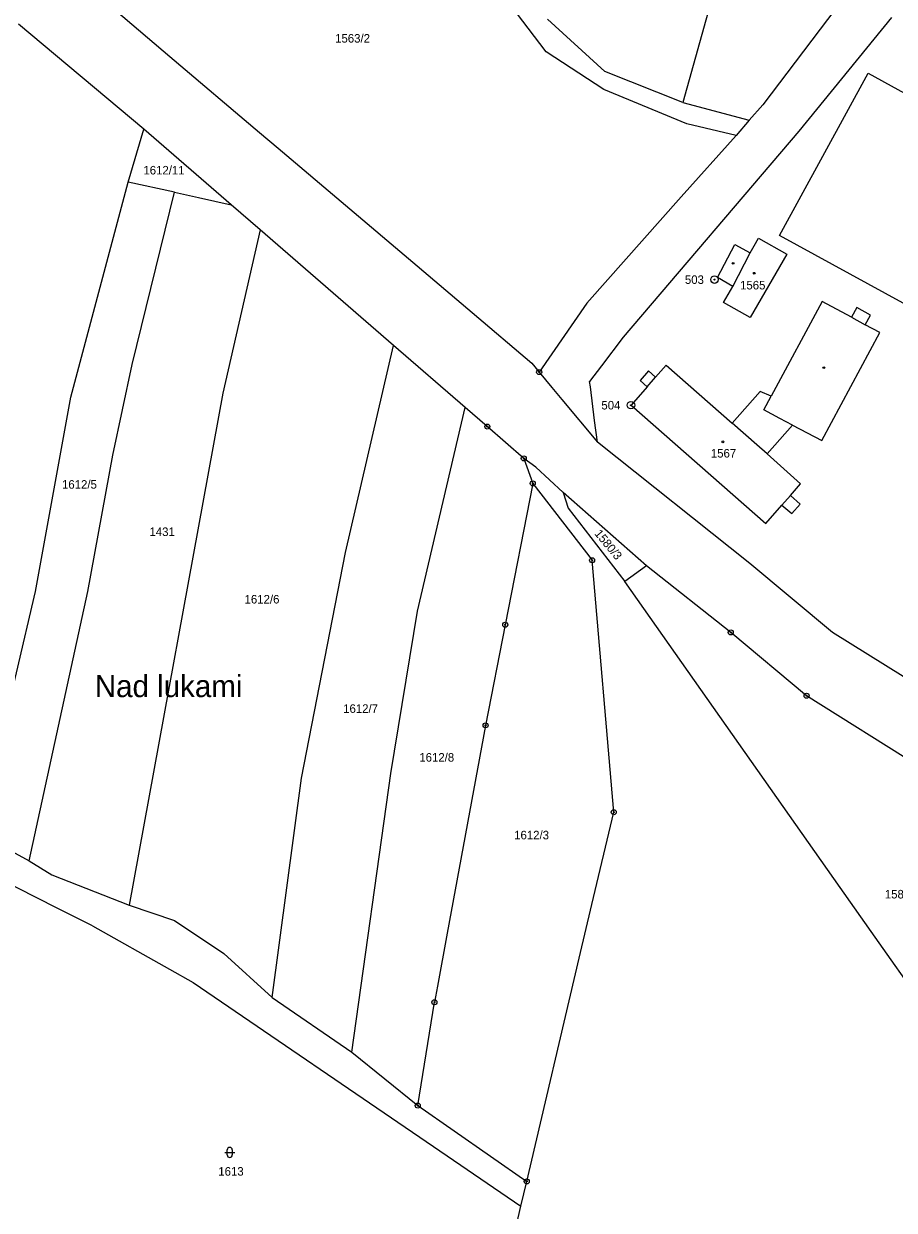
# Model space of a CAD drawing. Extents: x -763296 to -761805, y -1153670 to -1152034.
# Drawn here: x -762549.1 to -762375.6, y -1152539 to -1152302.6 of the extents above; entities that cross this region are included whole.
import ezdxf

# ---------------------------------------------------------------- set-up
doc = ezdxf.new("R2010")
doc.units = 0
for name, color, linetype in [('Vrstva 1', 7, 'Continuous'), ('Vrstva 15', 7, 'Continuous'), ('Vrstva 17', 7, 'Continuous'), ('Vrstva 18', 7, 'Continuous'), ('Vrstva 19', 7, 'Continuous'), ('Vrstva 24', 7, 'Continuous'), ('Vrstva 25', 7, 'Continuous'), ('Vrstva 4', 7, 'Continuous'), ('Vrstva 6', 7, 'Continuous')]:
    doc.layers.add(name, color=color, linetype=linetype)

msp = doc.modelspace()

# ---------------------------------------------------------------- linework, layer by layer
at = {"layer": 'Vrstva 1'}
for p, q in [((-762541.7, -1152290.61), (-762519.96, -1152309.07)), ((-762384.25, -1152295.59), (-762401.81, -1152318.76)), ((-762525.16, -1152323.58), (-762550.16, -1152302.68)), ((-762376.16, -1152301.32), (-762394.59, -1152324.01)), ((-762519.96, -1152309.07), (-762502.08, -1152324.24)), ((-762398.44, -1152344.76), (-762380.75, -1152312.44)), ((-762380.75, -1152312.44), (-762350.33, -1152329.15)), ((-762401.81, -1152318.76), (-762404.52, -1152321.81)), ((-762507.77, -1152338.63), (-762525.16, -1152323.58)), ((-762404.52, -1152321.81), (-762407.09, -1152324.84)), ((-762502.08, -1152324.24), (-762498.38, -1152327.38)), ((-762394.59, -1152324.01), (-762429.64, -1152365.01)), ((-762407.09, -1152324.84), (-762418.03, -1152337.04)), ((-762498.38, -1152327.38), (-762471.57, -1152350.11)), ((-762418.03, -1152337.04), (-762436.86, -1152358.25)), ((-762501.98, -1152343.64), (-762507.77, -1152338.63)), ((-762475.37, -1152366.68), (-762501.98, -1152343.64)), ((-762360.92, -1152365.36), (-762398.44, -1152344.76)), ((-762410.8, -1152353.16), (-762407.36, -1152346.54)), ((-762407.36, -1152346.54), (-762404.3, -1152348.24)), ((-762404.3, -1152348.24), (-762403.53, -1152346.85)), ((-762403.53, -1152346.85), (-762402.67, -1152345.3)), ((-762402.67, -1152345.3), (-762397.02, -1152348.51)), ((-762397.02, -1152348.51), (-762404.32, -1152361.1)), ((-762471.57, -1152350.11), (-762459.73, -1152360.14)), ((-762407.77, -1152354.91), (-762410.8, -1152353.16)), ((-762409.64, -1152358.14), (-762407.77, -1152354.91)), ((-762436.86, -1152358.25), (-762446.36, -1152371.99)), ((-762404.32, -1152361.1), (-762409.64, -1152358.14)), ((-762389.92, -1152357.94), (-762400.1, -1152376.82)), ((-762384.11, -1152361.07), (-762389.92, -1152357.94)), ((-762383.07, -1152359.13), (-762384.11, -1152361.07)), ((-762380.31, -1152360.62), (-762383.07, -1152359.13)), ((-762459.73, -1152360.14), (-762447.82, -1152370.24)), ((-762381.35, -1152362.56), (-762380.31, -1152360.62)), ((-762390.04, -1152385.62), (-762378.45, -1152364.12)), ((-762378.45, -1152364.12), (-762381.35, -1152362.56)), ((-762429.64, -1152365.01), (-762433.93, -1152370.74)), ((-762461.12, -1152379.02), (-762475.37, -1152366.68)), ((-762447.82, -1152370.24), (-762446.36, -1152371.99)), ((-762433.93, -1152370.74), (-762436.3, -1152373.89)), ((-762421.04, -1152370.62), (-762423.15, -1152373.01)), ((-762421.04, -1152370.62), (-762407.87, -1152382.18)), ((-762446.36, -1152371.99), (-762443.81, -1152375.06)), ((-762424.58, -1152371.75), (-762426.25, -1152373.65)), ((-762423.15, -1152373.01), (-762424.58, -1152371.75)), ((-762443.81, -1152375.06), (-762441.82, -1152377.45)), ((-762436.16, -1152374.96), (-762436.3, -1152373.89)), ((-762435.3, -1152381.66), (-762436.16, -1152374.96)), ((-762424.82, -1152374.91), (-762428.05, -1152378.58)), ((-762426.25, -1152373.65), (-762424.82, -1152374.91)), ((-762402.31, -1152375.88), (-762407.87, -1152382.18)), ((-762400.1, -1152376.82), (-762402.31, -1152375.88)), ((-762441.82, -1152377.45), (-762434.75, -1152385.96)), ((-762456.69, -1152382.85), (-762461.12, -1152379.02)), ((-762428.05, -1152378.58), (-762401.2, -1152402.17)), ((-762449.42, -1152389.19), (-762456.69, -1152382.85)), ((-762434.75, -1152385.96), (-762435.3, -1152381.66)), ((-762400.94, -1152388.31), (-762395.85, -1152382.56)), ((-762395.85, -1152382.56), (-762390.04, -1152385.62)), ((-762404.36, -1152410.13), (-762434.75, -1152385.96)), ((-762447, -1152390.96), (-762449.42, -1152389.19)), ((-762449.42, -1152389.19), (-762447.63, -1152394.18)), ((-762394.24, -1152394.24), (-762400.94, -1152388.31)), ((-762441.55, -1152395.98), (-762447, -1152390.96)), ((-762447.63, -1152394.18), (-762453.12, -1152422.34)), ((-762447.63, -1152394.18), (-762435.8, -1152409.5)), ((-762396.29, -1152396.58), (-762394.24, -1152394.24)), ((-762441.55, -1152395.98), (-762440.61, -1152399.1)), ((-762424.94, -1152410.59), (-762441.55, -1152395.98)), ((-762394.34, -1152398.3), (-762396.29, -1152396.58)), ((-762440.61, -1152399.1), (-762429.27, -1152413.7)), ((-762401.2, -1152402.17), (-762397.97, -1152398.49)), ((-762397.97, -1152398.49), (-762396.01, -1152400.2)), ((-762396.01, -1152400.2), (-762394.34, -1152398.3)), ((-762431.5, -1152459.7), (-762435.8, -1152409.5)), ((-762424.94, -1152410.59), (-762429.27, -1152413.7)), ((-762408.18, -1152423.87), (-762424.94, -1152410.59)), ((-762387.9, -1152423.92), (-762404.36, -1152410.13)), ((-762386.35, -1152474.7), (-762429.27, -1152413.7)), ((-762453.12, -1152422.34), (-762457.04, -1152442.39)), ((-762393.06, -1152436.49), (-762408.18, -1152423.87)), ((-762370.2, -1152434.94), (-762387.9, -1152423.92)), ((-762370.42, -1152450.7), (-762393.06, -1152436.49)), ((-762457.04, -1152442.39), (-762464.69, -1152483.78)), ((-762435.83, -1152478.1), (-762431.5, -1152459.7)), ((-762542.4, -1152478.84), (-762557.33, -1152471.3)), ((-762379.39, -1152484.58), (-762386.35, -1152474.7)), ((-762535.41, -1152482.36), (-762542.4, -1152478.84)), ((-762438.36, -1152488.8), (-762435.83, -1152478.1)), ((-762535.41, -1152482.36), (-762520.04, -1152490.99)), ((-762464.69, -1152483.78), (-762466.64, -1152494.34)), ((-762364.92, -1152505.15), (-762379.39, -1152484.58)), ((-762448.83, -1152533.27), (-762438.36, -1152488.8)), ((-762520.04, -1152490.99), (-762515.34, -1152493.63)), ((-762515.34, -1152493.63), (-762467.4, -1152526.31)), ((-762466.64, -1152494.34), (-762467.24, -1152497.57)), ((-762470.56, -1152518.17), (-762467.24, -1152497.57)), ((-762470.56, -1152518.17), (-762448.83, -1152533.27)), ((-762467.4, -1152526.31), (-762449.99, -1152538.18)), ((-762449.99, -1152538.18), (-762448.83, -1152533.27)), ((-762451.46, -1152544.43), (-762449.99, -1152538.18))]:
    msp.add_line(p, q, dxfattribs=at)
at = {"layer": 'Vrstva 24'}
for centre, radius in [((-762411.41, -1152353.57), 0.75), ((-762411.41, -1152353.57), 0.1), ((-762446.36, -1152371.99), 0.5), ((-762446.36, -1152371.99), 0.1), ((-762428.06, -1152378.59), 0.75), ((-762428.06, -1152378.59), 0.1), ((-762456.69, -1152382.85), 0.5), ((-762456.69, -1152382.85), 0.1), ((-762449.42, -1152389.19), 0.5), ((-762449.42, -1152389.19), 0.1), ((-762447.63, -1152394.18), 0.5), ((-762447.63, -1152394.18), 0.1), ((-762435.8, -1152409.5), 0.5), ((-762435.8, -1152409.5), 0.1), ((-762453.12, -1152422.34), 0.5), ((-762453.12, -1152422.34), 0.1), ((-762408.18, -1152423.87), 0.5), ((-762408.18, -1152423.87), 0.1), ((-762393.06, -1152436.49), 0.5), ((-762393.06, -1152436.49), 0.1), ((-762457.04, -1152442.39), 0.5), ((-762457.04, -1152442.39), 0.1), ((-762431.5, -1152459.7), 0.5), ((-762431.5, -1152459.7), 0.1), ((-762467.24, -1152497.57), 0.5), ((-762467.24, -1152497.57), 0.1), ((-762470.56, -1152518.17), 0.5), ((-762470.56, -1152518.17), 0.1), ((-762448.83, -1152533.27), 0.5), ((-762448.83, -1152533.27), 0.1)]:
    msp.add_circle(centre, radius, dxfattribs=at)
at = {"layer": 'Vrstva 25'}
for p, q in [((-762508.53, -1152528.01), (-762508.53, -1152527.01)), ((-762507.53, -1152527.01), (-762507.53, -1152528.01)), ((-762509.03, -1152527.51), (-762507.03, -1152527.51))]:
    msp.add_line(p, q, dxfattribs=at)
for centre in [(-762407.7, -1152350.32), (-762403.49, -1152352.3), (-762389.62, -1152371.11), (-762409.73, -1152385.89)]:
    msp.add_circle(centre, 0.175, dxfattribs=at)
for centre, start, end in [((-762508.03, -1152527.01), 0, 180), ((-762508.03, -1152528.01), 180, 0)]:
    msp.add_arc(centre, 0.5, start, end, dxfattribs=at)
at = {"layer": 'Vrstva 4'}
for p, q in [((-762407.77, -1152354.91), (-762404.3, -1152348.24)), ((-762384.11, -1152361.07), (-762381.35, -1152362.56)), ((-762424.82, -1152374.91), (-762423.15, -1152373.01)), ((-762401.55, -1152379.51), (-762400.1, -1152376.82)), ((-762398.36, -1152381.24), (-762401.55, -1152379.51)), ((-762403, -1152386.49), (-762407.87, -1152382.18)), ((-762395.85, -1152382.56), (-762398.36, -1152381.24)), ((-762400.94, -1152388.31), (-762403, -1152386.49)), ((-762397.97, -1152398.49), (-762396.29, -1152396.58))]:
    msp.add_line(p, q, dxfattribs=at)
at = {"layer": 'Vrstva 6'}
for p, q in [((-762444.95, -1152308.18), (-762456.19, -1152293.37)), ((-762411.77, -1152296.98), (-762417.72, -1152318.29)), ((-762433.24, -1152312.08), (-762444.73, -1152301.68)), ((-762433.46, -1152315.71), (-762444.95, -1152308.18)), ((-762417.72, -1152318.29), (-762433.24, -1152312.08)), ((-762416.95, -1152322.5), (-762433.46, -1152315.71)), ((-762417.72, -1152318.29), (-762404.52, -1152321.81)), ((-762528.29, -1152334.15), (-762525.16, -1152323.58)), ((-762407.09, -1152324.84), (-762416.95, -1152322.5)), ((-762539.73, -1152377.02), (-762528.29, -1152334.15)), ((-762519.01, -1152336.13), (-762528.29, -1152334.15)), ((-762527.46, -1152370.47), (-762519.01, -1152336.13)), ((-762519.01, -1152336.13), (-762514.23, -1152337.21)), ((-762514.23, -1152337.21), (-762507.77, -1152338.63)), ((-762501.98, -1152343.64), (-762509.41, -1152376.21)), ((-762484.99, -1152407.93), (-762475.37, -1152366.68)), ((-762531.31, -1152388.52), (-762527.46, -1152370.47)), ((-762546.74, -1152415.72), (-762539.73, -1152377.02)), ((-762509.41, -1152376.21), (-762528.09, -1152478.26)), ((-762470.63, -1152419.61), (-762461.12, -1152379.02)), ((-762536.3, -1152415.72), (-762531.31, -1152388.52)), ((-762493.74, -1152452.93), (-762484.99, -1152407.93)), ((-762558.07, -1152463.9), (-762546.74, -1152415.72)), ((-762548.03, -1152469.36), (-762536.3, -1152415.72)), ((-762475.95, -1152451.99), (-762470.63, -1152419.61)), ((-762499.56, -1152496.6), (-762493.74, -1152452.93)), ((-762483.73, -1152507.49), (-762475.95, -1152451.99)), ((-762558.07, -1152463.9), (-762548.03, -1152469.36)), ((-762548.03, -1152469.36), (-762543.49, -1152472.16)), ((-762543.49, -1152472.16), (-762528.09, -1152478.26)), ((-762528.09, -1152478.26), (-762519.05, -1152481.25)), ((-762519.05, -1152481.25), (-762509.2, -1152487.88)), ((-762509.2, -1152487.88), (-762499.56, -1152496.6)), ((-762499.56, -1152496.6), (-762483.73, -1152507.49)), ((-762483.73, -1152507.49), (-762470.56, -1152518.17))]:
    msp.add_line(p, q, dxfattribs=at)

# ---------------------------------------------------------------- texts
at = {"layer": 'Vrstva 15'}
msp.add_text('Nad lukami', height=4.4, dxfattribs=at).set_placement((-762534.934, -1152436.77))
at = {"layer": 'Vrstva 17'}
for s, p in [('503', (-762417.311, -1152354.42)), ('504', (-762433.961, -1152379.44))]:
    msp.add_text(s, height=1.7, dxfattribs=at).set_placement(p)
at = {"layer": 'Vrstva 18'}
for s, p in [('1563/2', (-762487.032, -1152306.33)), ('1612/11', (-762525.243, -1152332.61)), ('1612/5', (-762541.467, -1152395.23)), ('1431', (-762524.034, -1152404.66)), ('1612/6', (-762505.08, -1152418.11)), ('1612/7', (-762485.43, -1152439.9)), ('1612/8', (-762470.25, -1152449.62)), ('1612/3', (-762451.347, -1152465.11)), ('1580/2', (-762377.468, -1152476.89)), ('1613', (-762510.314, -1152532.13))]:
    msp.add_text(s, height=1.7, dxfattribs=at).set_placement(p)
msp.add_text('1580/3', height=1.7, rotation=309.62639, dxfattribs=at).set_placement((-762435.437, -1152404.228))
at = {"layer": 'Vrstva 19'}
for s, p in [('1565', (-762406.319, -1152355.52)), ('1567', (-762412.142, -1152389.02))]:
    msp.add_text(s, height=1.7, dxfattribs=at).set_placement(p)

doc.saveas('drawing.dxf')
